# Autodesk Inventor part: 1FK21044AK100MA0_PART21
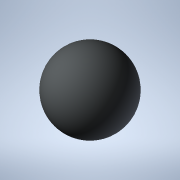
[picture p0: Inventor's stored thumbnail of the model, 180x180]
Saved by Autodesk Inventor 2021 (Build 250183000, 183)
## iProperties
Created: 2025-04
Part Number: 1FK21044AK100MA0_PART21
Material: Generic
Catalog Web Link: www.3dfindit.com
Description: -Servo synchronous motor
Document SubType Name: Modeling
Designer: psAdmin
Mass: 0.137258 g
Surface Area: 1.2868 cm^2
Volume: 0.137258 cm^3
Density: 1 g/cm^3
Appearance: PSOLRGB-212-217-219
Category: PARTsolutions
Title: 1FK21044AK100MA0_PART21
Author: Cadenas PARTsolutions
Comments: Servo synchronous motor
Sending System: PARTsolutions
Preprocessor: ST-DEVELOPER v19.3
PSOL_IDENT_0: {$CADENAS_DATA/23d-libs/siemens_ag/_cat_/5e/d8/1fk21044ak100ma0.prj},216 {VTYP=3D},{NB=1FK21044AK100
PSOL_IDENT_1: MA0_PART21},{LINA=1FK21044AK100MA0_PART21},{NN=1FK21044AK100MA0_PART21},{NOPRJ=TRUE},{DATE=19.08.202
PSOL_IDENT_2: 5 14:00:41},{GEOMDATE=30.07.2025 02:00:53},{VERSION=},{LINEID=10},{WBVAR=},{WBNUMERIC=}  {NB=1FK2104
PSOL_IDENT_3: 4AK100MA0_PART21},{LINA=1FK21044AK100MA0_PART21},{KT=DUMMY},{PREVIEW=../../../_pool_/cb/72/p_d211_xx
PSOL_IDENT_4: _00434j.png},{DESCSHORT=SIMOTICS S-1FK2 HD, SINAMICS S210 3AC 400V-480V, 0.95 Nm, 6000 rpm},{DESCLON
PSOL_IDENT_5: G=SIMOTICS S-1FK2 HD servo motor M0=1.27 Nm; PN = 0.6 kW at nN=6000 rpm (380-480 V); PN = 0.4 kW at
PSOL_IDENT_6: nN=3000 rpm (200-240 V); with holding brake; degree of protection IP64; cylindrical shaft D19x40mm;
PSOL_IDENT_7: absolute encoder 22-bit + 12-bit multiturn (encoder AM22DQC); with OCC interface; plug size M17, rot
PSOL_IDENT_8: atable; SIMOTICS S-1FK2 servomotorfor a wide range of uses in industrial environments. SIMOTICS S‑1F
PSOL_IDENT_9: K2 servomotors are compact synchronous motors with a high dynamic performance that set themselves ap
PSOL_IDENT_10: art as a result of their high power density, degree of protection and overload capability. The motor
PSOL_IDENT_11: s are available in two variants: as High Dynamic variant (highest dynamic performance as a result of
PSOL_IDENT_12: the low intrinsic moment of inertia for applications demanding a high dynamic performance with low
PSOL_IDENT_13: moved masses) - and as Compact variant (precise and stable closed-loop control for medium up to larg
PSOL_IDENT_14: e moved masses as a result of a medium intrinsic moment of inertia). SIMOTICSS‑1FK2 servomotors full
PSOL_IDENT_15: y exploit their strengths in a system with the SINAMICSS210 frequency converter and simple connectio
PSOL_IDENT_16: n using the one cable connection (OCC). Advantages include the short control and positioning times,
PSOL_IDENT_17: fast and precise correction of disturbing quantities as well as stable control with a high dynamic p
PSOL_IDENT_18: erformance. The servo motors can be configured to address a wide range of requirements. For example
PSOL_IDENT_19: with and without holding brake, IP64 or IP65 degree of protection, singleturn or multiturn absolute
PSOL_IDENT_20: encoders - to name just a few. Further, the servomotors are available in different shaft heights ext
PSOL_IDENT_21: ending from 20 to 100. A shaft sealing ring is available to achieve an IP65 degree of protection and
PSOL_IDENT_22: for subsequent mounting at the motor or as spare part. SIMOTICS - the optimum motor for each and ev
PSOL_IDENT_23: ery motion control application.},{INTNO=804766910005},{SUPPLIERALTNO=1FK2104-4AK10-0MA0},{MANUID=1FK
PSOL_IDENT_24: 21044AK100MA0},{MANUNAME=Siemens},{MANUTYPEDESC=Synchronous motor 1FK2-HD 1,27 Nm},{AAU732=SIMOTICS}
PSOL_IDENT_25: ,{AAO057=S-1FK2},{AAU734=SIMOTICS S-1FK2 HD servo motor M0=1.27 Nm; PN = 0.6 kW at nN=6000 rpm (380-
PSOL_IDENT_26: 480 V); PN = 0.4 kW at nN=3000 rpm (200-240 V); with holding brake; degree of protection IP64; cylin
PSOL_IDENT_27: drical shaft D19x40mm; absolute encoder 22-bit + 12-bit multiturn (encoder AM22DQC); with OCC interf
PSOL_IDENT_28: ace; plug size M17, rotatable;},{AAW338=Synchronous motor 1FK2-HD 1,27 Nm},{AAO742=SIMOTICS},{AAO663=
PSOL_IDENT_29: 4042948691076},{NOCUPEROU=1},{PRICEQUANTITY=1},{QUANTITYMIN=1},{QUANTITYINT=1},{CTN=85015100},{COO=D
PSOL_IDENT_30: E},{AAO676=1FK2104-4AK10-0MA0},{AAO677=Siemens AG},{ORDERUNIT=C62},{CONTENTUNIT=C62}
NB: 1FK21044AK100MA0_PART21
NT: Servo synchronous motor
NBSYN: $MANUID._PART21
LINA: 1FK21044AK100MA0_PART21
CATALOG: SIEMENS
PREVIEW: ../../../_pool_/cb/72/p_d211_xx_00434j.png
DESCSHORT: SIMOTICS S-1FK2 HD, SINAMICS S210 3AC 400V-480V, 0.95 Nm, 6000 rpm
DESCLONG: SIMOTICS S-1FK2 HD servo motor M0=1.27 Nm; PN = 0.6 kW at nN=6000 rpm (380-480 V); PN = 0.4 kW at nN=3000 rpm (200-240 V); with holding brake; degree of protect
INTNO: 804766910005
SUPPLIERALTNO: 1FK2104-4AK10-0MA0
MANUID: 1FK21044AK100MA0
MANUNAME: Siemens
MANUTYPEDESC: Synchronous motor 1FK2-HD 1,27 Nm
AAU732: SIMOTICS
AAO057: S-1FK2
AAU734: SIMOTICS S-1FK2 HD servo motor M0=1.27 Nm; PN = 0.6 kW at nN=6000 rpm (380-480 V); PN = 0.4 kW at nN=3000 rpm (200-240 V); with holding brake; degree of protect
AAW338: Synchronous motor 1FK2-HD 1,27 Nm
AAO742: SIMOTICS
AAO663: 4042948691076.0
NOCUPEROU: 1
PRICEQUANTITY: 1
QUANTITYMIN: 1
QUANTITYINT: 1
CTN: 85015100
COO: DE
ARTICLENO: 1FK21044AK100MA0_PART21
BOMINFO: 1FK21044AK100MA0_PART21
CREATOR: CADENAS GmbH
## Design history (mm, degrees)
feature "2025_04_17_15_35_41_0968"
body "Solid1"
